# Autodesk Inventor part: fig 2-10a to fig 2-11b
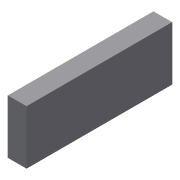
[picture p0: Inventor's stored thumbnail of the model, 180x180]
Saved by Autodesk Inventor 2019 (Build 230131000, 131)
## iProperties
Created: 2011-06
Part Number: fig 2-10a to fig 2-11b
Material: Generic
Document SubType Name: Modeling
Designer: CadCim
Density: 1 g/cm^3
Appearance: Default
Author: CadCim
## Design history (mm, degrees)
sketch "Sketch1"
  geometry: 1 further point
sketch "Sketch2"
  geometry: L1 (-35, 13)-(0, 13); L2 (0, 13)-(0, 0); L3 (0, 0)-(-35, 0); L4 (-35, 0)-(-35, 13); 1 further point
  constraints: 8 end point, 2 parallel, 1 coincident, 1 horizontal, 1 perpendicular
extrude "Extrusion1" new body sketch "Sketch2" distance "d0" = 4.5; taper "d1" = 0 deg
body "Solid1"
